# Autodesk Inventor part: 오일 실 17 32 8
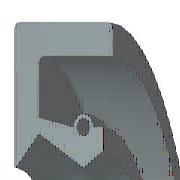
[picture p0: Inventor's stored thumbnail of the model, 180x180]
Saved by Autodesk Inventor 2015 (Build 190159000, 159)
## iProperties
IsCustomPart: 0
Created: 2018-09
Part Number: 오일 실 17 32 8
Material: 고무
Description: 오일-실
Document SubType Name: Modeling
Standard: KS B 2804
Standards Organization: KS
Language: ko-KR
Size Designation: D - 17 32 8
Categories: <MemberInstance><Categories><Category DisplayName="샤프트 부품" InternalName="7f7aeb1f-a693-4053-b835-cee3144e0d98" Mnemonic="SHFT"><Category DisplayName="실링" Intern
Density: 0.93 g/cm^3
Appearance: 고무 - 검은색 - 버전 1.1
Mass: 2.28027 g
Surface Area: 32.1224 cm^2
Volume: 2.45191 cm^3
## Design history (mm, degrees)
revolve "본체" stored, may be unused: angle "d17" = 90 deg
revolve "스프링1" stored, may be unused: angle "d18" = 90 deg
body "Solid1"
sketch "스케치1"
  geometry: L1 (0, 16)-(8, 16); L2 (8, 14.25)-(1.75, 14.25); L3 (1.75, 10.25)-(4.9, 8.5); L4 (4.9, 8.5)-(0, 8.5); L5 (0, 0)-(9.586, 0) reference; L6 (4.9, 8.5)-(6.3, 9.375); L7 (0, 18)-(0, -3) reference; L8 (-1.941, 0)-(11.507, 0) reference; L9 (4.2, 10.6)-(1.75, 11.21); L10 (1.75, 11.21)-(1.75, 14.25); L11 (0, 16)-(0, 8.588); L12 (4.9, 8.5)-(0, 8.5); L13 (1.75, 10.25)-(0.152, 8.528); L14 (8, 16)-(8, 14.25); L15 (5.6, 10.6)-(6.3, 10.6); L16 (6.3, 10.6)-(6.3, 9.375); C1 r 0.455 at (4.9, 10.6); A1 r 0.7 centre (4.9, 10.6) between (5.6, 10.6) and (4.2, 10.6); A2 r 0.088 centre (0.088, 8.588) between (0, 8.588) and (0.152, 8.528); 1 further point
  constraints: 28 end point, 5 horizontal alignment, 5 point on line, 4 point on circle, 4 vertical alignment, 3 centre point, 3 tangent, 2 collinear, 2 horizontal, 2 perpendicular, 1 coincident, 1 parallel
  dimensions: "d0" = 32 diameter of L1 L5 (= SD2); "d1" = 1.75 distance of L1.end L2.start (= SD); "d2" = 0.91 diameter of C1 (= SPDI); "d3" = 1.4 diameter of A1 (= SPDA); "d4" = 17 diameter of L3.end L5 (= NND); "d5" = 20.5 diameter of L3.start L5 (= TKDM); "d7" = 22.42 diameter of L9.end L5 (= TKDM + 0.24 x SWDT); "d8" = 1.75 distance between parallel lines of L11 L10 (= SD); "d9" = 4.9 distance from line of L11 C1.centre (= SPDST); "d10" = 21.2 diameter of C1.centre L5 (= HLDM); "d11" = 0.0875 radius of A2 (= 0.25 x LAB); "d12" = 6.3 distance between parallel lines of L11 L16 (= SDI); "d13" = 18.75 diameter of L6.end L5 (= ABDM); "d14" = 8 distance from line of L11 L1.end (= SWDT)
fillet "모깎기1" dims "d6" = 0.3 (= RR)
other parameters: "SD2" = 32 [user parameter; used in 1 equation term], "SWDT" = 8 [user parameter; used in 2 equation terms], "RR" = 0.3 [user parameter; used in 1 equation term], "SD" = 1.75 [user parameter; used in 2 equation terms], "NND" = 17 [user parameter; used in 1 equation term], "SPDA" = 1.4 [user parameter; used in 1 equation term], "SPDI" = 0.91 [user parameter; used in 1 equation term], "TKDM" = 20.5 [user parameter; used in 2 equation terms], "HLDM" = 21.2 [user parameter; used in 1 equation term], "ABDM" = 18.75 [user parameter; used in 1 equation term], "SDI" = 6.3 [user parameter; used in 1 equation term], "SPDST" = 4.9 [user parameter; used in 1 equation term], "LAB" = 0.35 [user parameter; used in 1 equation term], "d15" = 0, "d16" = 0, "d19" = 0
